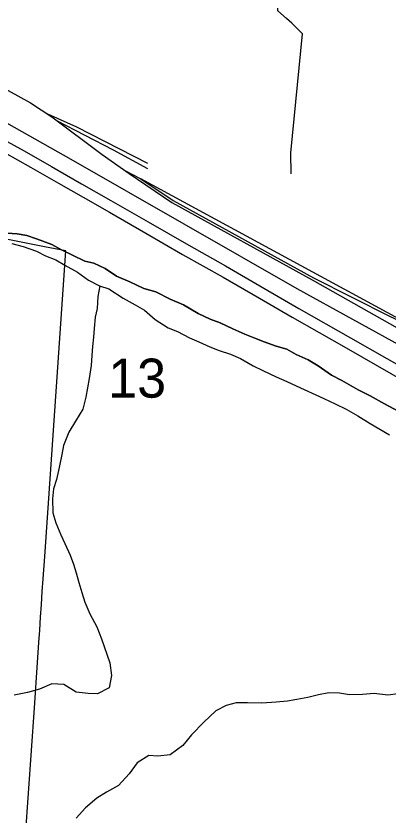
# Model space of a CAD drawing. Extents: x 39.8 to 73.8, y 13 to 35.
# Drawn here: x 42.92 to 43.32, y 31.214 to 32.071 of the extents above; entities that cross this region are included whole.
import ezdxf

# ---------------------------------------------------------------- set-up
doc = ezdxf.new("R2010")
doc.units = 0
for name, color, linetype in [('GM_X_City_Street', 7, 'Continuous'), ('GM_X_Corporation', 7, 'Continuous'), ('GM_X_Major_River', 7, 'Continuous'), ('GM_X_Minor_River', 7, 'Continuous'), ('GM_X_Rail_Line', 7, 'Continuous'), ('GM_X_Section_Text', 7, 'Continuous'), ('GM_X_US_Route', 7, 'Continuous')]:
    doc.layers.add(name, color=color, linetype=linetype)

msp = doc.modelspace()

# ---------------------------------------------------------------- linework, layer by layer
at = {"layer": 'GM_X_City_Street'}
msp.add_lwpolyline([(43.21538, 31.90211), (43.21508, 31.92451), (43.22773, 32.05241), (43.21637, 32.06382), (43.2106, 32.0689), (43.20122, 32.07714), (43.202, 32.11964), (43.20219, 32.1299), (43.21117, 32.18714), (43.21017, 32.23675), (43.21343, 32.28817)], dxfattribs=at)
at = {"layer": 'GM_X_Corporation'}
for points in [[(42.89538, 31.96481), (42.97877, 31.91806), (43.22159, 31.77899), (43.46061, 31.64769), (43.48983, 31.63401), (43.49632, 31.62962), (43.5022, 31.62534), (43.59082, 31.5773), (43.64405, 31.54814), (43.7148, 31.5014), (43.71532, 31.50813), (43.9529, 31.37562)], [(42.91598, 30.94323), (42.9303, 31.192), (42.93978, 31.32942), (42.9431, 31.37789), (42.94457, 31.39925), (42.94549, 31.41276), (42.94645, 31.42674), (42.94737, 31.44016), (42.94832, 31.45414), (42.94926, 31.46775), (42.9509, 31.49174), (42.97344, 31.8194), (42.95057, 31.8239), (42.89843, 31.83416)]]:
    msp.add_lwpolyline(points, dxfattribs=at)
at = {"layer": 'GM_X_Major_River'}
for p, q in [((42.92117, 31.83781), (42.91057, 31.83857)), ((42.93176, 31.83592), (42.92117, 31.83781)), ((42.94199, 31.83251), (42.93176, 31.83592)), ((42.91549, 31.82758), (42.9276, 31.82417)), ((42.95864, 31.82645), (42.94199, 31.83251)), ((42.96887, 31.82076), (42.95864, 31.82645)), ((42.9276, 31.82417), (42.94198, 31.81924)), ((42.94198, 31.81924), (42.95183, 31.81432)), ((42.9806, 31.81508), (42.96887, 31.82076)), ((42.95183, 31.81432), (42.9628, 31.80977)), ((42.9628, 31.80977), (42.97265, 31.80409)), ((42.99385, 31.80864), (42.9806, 31.81508)), ((42.97265, 31.80409), (42.98627, 31.79651)), ((43.00369, 31.80637), (42.99385, 31.80864)), ((43.0158, 31.80068), (43.00369, 31.80637)), ((43.02792, 31.79235), (43.0158, 31.80068)), ((42.98627, 31.79651), (42.99801, 31.78817)), ((43.0423, 31.78628), (43.02792, 31.79235)), ((42.99801, 31.78817), (43.00974, 31.78211)), ((43.05744, 31.77909), (43.0423, 31.78628)), ((43.00974, 31.78211), (43.01958, 31.7787)), ((43.01958, 31.7787), (43.0351, 31.76885)), ((43.07031, 31.77568), (43.05744, 31.77909)), ((43.08546, 31.76772), (43.07031, 31.77568)), ((43.0351, 31.76885), (43.04797, 31.76165)), ((43.09984, 31.76166), (43.08546, 31.76772)), ((43.04797, 31.76165), (43.05819, 31.75597)), ((43.11574, 31.75219), (43.09984, 31.76166)), ((43.05819, 31.75597), (43.06955, 31.74574)), ((43.12861, 31.74613), (43.11574, 31.75219)), ((43.06955, 31.74574), (43.08355, 31.73702)), ((43.13921, 31.74234), (43.12861, 31.74613)), ((43.15283, 31.7359), (43.13921, 31.74234)), ((43.08355, 31.73702), (43.0934, 31.73285)), ((43.0934, 31.73285), (43.10627, 31.72641)), ((43.16571, 31.73021), (43.15283, 31.7359)), ((43.10627, 31.72641), (43.11649, 31.72187)), ((43.17669, 31.72605), (43.16571, 31.73021)), ((43.18653, 31.72188), (43.17669, 31.72605)), ((43.11649, 31.72187), (43.12822, 31.71656)), ((43.12822, 31.71656), (43.13807, 31.71277)), ((43.1994, 31.71733), (43.18653, 31.72188)), ((43.21075, 31.71392), (43.1994, 31.71733)), ((43.13807, 31.71277), (43.15056, 31.70861)), ((43.15056, 31.70861), (43.16116, 31.70406)), ((43.22097, 31.70824), (43.21075, 31.71392)), ((43.23384, 31.70256), (43.22097, 31.70824)), ((43.16116, 31.70406), (43.17478, 31.69611)), ((43.24444, 31.69611), (43.23384, 31.70256)), ((43.17478, 31.69611), (43.18501, 31.69118)), ((43.18501, 31.69118), (43.19939, 31.68436)), ((43.25883, 31.68626), (43.24444, 31.69611)), ((43.19939, 31.68436), (43.21074, 31.67943)), ((43.2698, 31.68058), (43.25883, 31.68626)), ((43.2876, 31.67035), (43.2698, 31.68058)), ((43.21074, 31.67943), (43.22097, 31.67489)), ((43.22097, 31.67489), (43.25049, 31.66125)), ((43.30047, 31.66391), (43.2876, 31.67035)), ((43.31561, 31.65557), (43.30047, 31.66391)), ((43.25049, 31.66125), (43.26298, 31.65557)), ((43.26298, 31.65557), (43.27472, 31.64988)), ((43.33113, 31.64724), (43.31561, 31.65557)), ((43.27472, 31.64988), (43.28721, 31.64268)), ((43.28721, 31.64268), (43.30046, 31.63435)), ((43.30046, 31.63435), (43.31068, 31.62828)), ((43.31068, 31.62828), (43.32128, 31.62222))]:
    msp.add_line(p, q, dxfattribs=at)
for points in [[(42.91057, 31.83857), (42.92117, 31.83781), (42.93176, 31.83592), (42.94199, 31.83251), (42.95864, 31.82645), (42.96887, 31.82076), (42.9806, 31.81508), (42.99385, 31.80864), (43.00369, 31.80637), (43.0158, 31.80068), (43.02792, 31.79235), (43.0423, 31.78628), (43.05744, 31.77909), (43.07031, 31.77568), (43.08546, 31.76772), (43.09984, 31.76166), (43.11574, 31.75219), (43.12861, 31.74613), (43.13921, 31.74234), (43.15283, 31.7359), (43.16571, 31.73021), (43.17669, 31.72605), (43.18653, 31.72188), (43.1994, 31.71733), (43.21075, 31.71392), (43.22097, 31.70824), (43.23384, 31.70256), (43.24444, 31.69611), (43.25883, 31.68626), (43.2698, 31.68058), (43.2876, 31.67035), (43.30047, 31.66391), (43.31561, 31.65557), (43.33113, 31.64724)], [(42.91549, 31.82758), (42.9276, 31.82417), (42.94198, 31.81924), (42.95183, 31.81432), (42.9628, 31.80977), (42.97265, 31.80409), (42.98627, 31.79651), (42.99801, 31.78817), (43.00974, 31.78211), (43.01958, 31.7787), (43.0351, 31.76885), (43.04797, 31.76165), (43.05819, 31.75597), (43.06955, 31.74574), (43.08355, 31.73702), (43.0934, 31.73285), (43.10627, 31.72641), (43.11649, 31.72187), (43.12822, 31.71656), (43.13807, 31.71277), (43.15056, 31.70861), (43.16116, 31.70406), (43.17478, 31.69611), (43.18501, 31.69118), (43.19939, 31.68436), (43.21074, 31.67943), (43.22097, 31.67489), (43.25049, 31.66125), (43.26298, 31.65557), (43.27472, 31.64988), (43.28721, 31.64268), (43.30046, 31.63435), (43.31068, 31.62828), (43.32128, 31.62222)]]:
    msp.add_lwpolyline(points, dxfattribs=at)
at = {"layer": 'GM_X_Minor_River'}
for p, q in [((43.01025, 31.78194), (43.00785, 31.77074)), ((43.00785, 31.77074), (43.00708, 31.75786)), ((43.00708, 31.75786), (43.00519, 31.74838)), ((43.00519, 31.74838), (43.00405, 31.73625)), ((43.00405, 31.73625), (43.00329, 31.72678)), ((43.00329, 31.72678), (43.00215, 31.71692)), ((43.00215, 31.71692), (43.00139, 31.70745)), ((43.00139, 31.70745), (43.00063, 31.69646)), ((43.00063, 31.69646), (42.99874, 31.68244)), ((42.99874, 31.68244), (42.99495, 31.66273)), ((42.99495, 31.66273), (42.99192, 31.64984)), ((42.99192, 31.64984), (42.98396, 31.63695)), ((42.98396, 31.63695), (42.97677, 31.6252)), ((42.97677, 31.6252), (42.97108, 31.6108)), ((42.97108, 31.6108), (42.96919, 31.60095)), ((42.96919, 31.60095), (42.96653, 31.5873)), ((42.96653, 31.5873), (42.9635, 31.57442)), ((42.9635, 31.57442), (42.96047, 31.56418)), ((42.96047, 31.56418), (42.95933, 31.55357)), ((42.95933, 31.55357), (42.95971, 31.53841)), ((42.95971, 31.53841), (42.96273, 31.5278)), ((42.96273, 31.5278), (42.96803, 31.51492)), ((42.96803, 31.51492), (42.97257, 31.50544)), ((42.97257, 31.50544), (42.97825, 31.49294)), ((42.97825, 31.49294), (42.98165, 31.48346)), ((42.98165, 31.48346), (42.98468, 31.47399)), ((42.98468, 31.47399), (42.9877, 31.46375)), ((42.9877, 31.46375), (42.99073, 31.45314)), ((42.99073, 31.45314), (42.99414, 31.44253)), ((42.99414, 31.44253), (42.99943, 31.43003)), ((42.99943, 31.43003), (43.007, 31.41638)), ((43.007, 31.41638), (43.01192, 31.4035)), ((43.01192, 31.4035), (43.021, 31.37773)), ((43.021, 31.37773), (43.02251, 31.36409)), ((43.02251, 31.36409), (43.02024, 31.35082)), ((42.95853, 31.35498), (42.94528, 31.34929)), ((42.9714, 31.35422), (42.95853, 31.35498)), ((42.94528, 31.34929), (42.9324, 31.34588)), ((42.98465, 31.34627), (42.9714, 31.35422)), ((42.99752, 31.34475), (42.98465, 31.34627)), ((43.02024, 31.35082), (43.00774, 31.34438)), ((42.9324, 31.34588), (42.91801, 31.34284)), ((43.00774, 31.34438), (42.99752, 31.34475)), ((43.22164, 31.33834), (43.21179, 31.33645)), ((43.23338, 31.34024), (43.22164, 31.33834)), ((43.24473, 31.34327), (43.23338, 31.34024)), ((43.25609, 31.34555), (43.24473, 31.34327)), ((43.26745, 31.34517), (43.25609, 31.34555)), ((43.27805, 31.34328), (43.26745, 31.34517)), ((43.29206, 31.34366), (43.27805, 31.34328)), ((43.30455, 31.3448), (43.29206, 31.34366)), ((43.31932, 31.3429), (43.30455, 31.3448)), ((43.33029, 31.34442), (43.31932, 31.3429)), ((43.14592, 31.33189), (43.13456, 31.3262)), ((43.15652, 31.33454), (43.14592, 31.33189)), ((43.16864, 31.33455), (43.15652, 31.33454)), ((43.18416, 31.33417), (43.16864, 31.33455)), ((43.1993, 31.33531), (43.18416, 31.33417)), ((43.21179, 31.33645), (43.1993, 31.33531)), ((43.13456, 31.3262), (43.12169, 31.31407)), ((43.12169, 31.31407), (43.10843, 31.30043)), ((43.10843, 31.30043), (43.09934, 31.28906)), ((43.09934, 31.28906), (43.08571, 31.27882)), ((43.06262, 31.27806), (43.05012, 31.27048)), ((43.07246, 31.2773), (43.06262, 31.27806)), ((43.08571, 31.27882), (43.07246, 31.2773)), ((43.05012, 31.27048), (43.04141, 31.25835)), ((43.04141, 31.25835), (43.03005, 31.24584)), ((43.03005, 31.24584), (43.01718, 31.23902)), ((43.01718, 31.23902), (43.00696, 31.23257)), ((43.00696, 31.23257), (42.99484, 31.22196)), ((42.99484, 31.22196), (42.98461, 31.21097))]:
    msp.add_line(p, q, dxfattribs=at)
at = {"layer": 'GM_X_Rail_Line'}
for p in [(43.03705, 31.90565), (43.35163, 31.73551)]:
    msp.add_line(p, (43.05405, 31.89694), dxfattribs=at)
for points in [[(42.90074, 31.99745), (42.93559, 31.9783), (42.95864, 31.96322), (43.01256, 31.92297), (43.04157, 31.90246), (43.08741, 31.87158), (43.23827, 31.78856), (43.34337, 31.7292), (43.42555, 31.68465), (43.44028, 31.67412), (43.46785, 31.65471), (43.48403, 31.64615), (43.79656, 31.47428), (43.9305, 31.401)], [(43.0618, 31.91338), (42.98539, 31.95218), (42.95423, 31.9661)], [(42.96363, 31.95949), (43.02427, 31.92776), (43.06143, 31.90788)], [(43.05405, 31.89694), (43.08867, 31.87362), (43.23944, 31.79065), (43.3219, 31.74913), (43.35163, 31.73551)]]:
    msp.add_lwpolyline(points, dxfattribs=at)
at = {"layer": 'GM_X_US_Route'}
for points in [[(42.74101, 31.99454), (42.76305, 31.98789), (42.79003, 31.9795), (42.81224, 31.97094), (42.83231, 31.96288), (42.8555, 31.95269), (42.89349, 31.93276), (42.93545, 31.90926), (42.96571, 31.89232), (42.99203, 31.87718), (43.02049, 31.8609), (43.05931, 31.83853), (43.09879, 31.81566), (43.14255, 31.79115), (43.1817, 31.76861), (43.21657, 31.74855), (43.27447, 31.71548), (43.3536, 31.67025), (43.44966, 31.6153), (43.4596, 31.60964), (43.50707, 31.58257), (43.53127, 31.56856)], [(42.89921, 31.9431), (42.92882, 31.92681), (42.9581, 31.91003), (42.99035, 31.89144), (43.02193, 31.87368), (43.06207, 31.85065), (43.10566, 31.82548), (43.14497, 31.8036), (43.1861, 31.77959), (43.22393, 31.75787), (43.27937, 31.72629), (43.35717, 31.68188), (43.46057, 31.62289), (43.50966, 31.59486), (43.57349, 31.55933), (43.63928, 31.5205), (43.69258, 31.48991), (43.73848, 31.46194), (43.78848, 31.4302), (43.82467, 31.40585), (43.86514, 31.37739), (43.90067, 31.35173), (43.93505, 31.32574)]]:
    msp.add_lwpolyline(points, dxfattribs=at)

# ---------------------------------------------------------------- texts
at = {"layer": 'GM_X_Section_Text'}
msp.add_text('13', height=0.041856, rotation=0.00001, dxfattribs=at).set_placement((43.01904, 31.66207))

doc.saveas('drawing.dxf')
